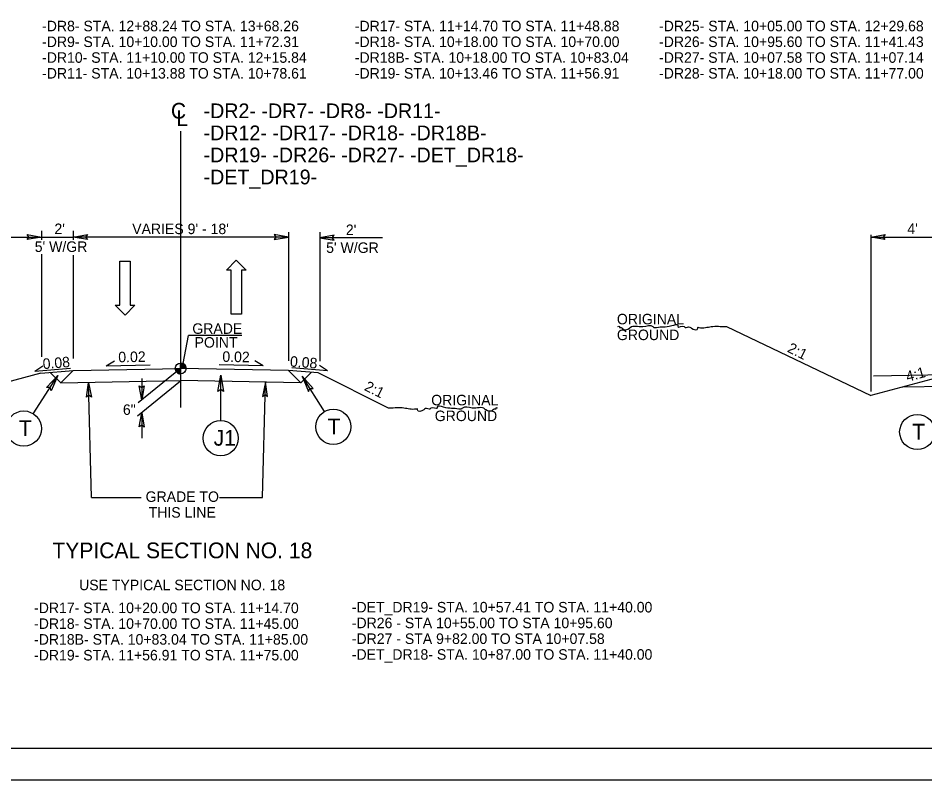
# Model space of a CAD drawing. Extents: x 18938 to 19565, y 6931 to 7973.
# Drawn here: x 19231 to 19317.4, y 6930.7 to 7003.2 of the extents above; entities that cross this region are included whole.
import ezdxf

# ---------------------------------------------------------------- set-up
doc = ezdxf.new("R2010")
doc.units = 0
for name, color, linetype in [('Old_Level_11', 7, 'Continuous'), ('Old_Level_2', 7, 'Continuous'), ('Old_Level_3', 7, 'Continuous'), ('Prop Dimension', 7, 'Continuous'), ('Prop Pavement Schedule Description CELL', 7, 'Continuous'), ('Prop Shade Medium', 7, 'Continuous'), ('Prop Terminator CELL', 7, 'Continuous'), ('Sheet Data Field CELL', 7, 'Continuous'), ('Sheet Plot Border Outside CELL', 7, 'Continuous'), ('Sheet Typical CELL', 7, 'Continuous'), ('Typical Curb CELL', 7, 'Continuous'), ('Typical Detail Wedge1 CELL', 7, 'Continuous'), ('Typical Detail Wedge2 CELL', 7, 'Continuous'), ('Typical Detail Wedge3 CELL', 7, 'Continuous'), ('Typical Guardrail CELL', 7, 'Continuous'), ('Typical Pavement Slope Information CELL', 7, 'Continuous'), ('Typical Shoulder Slope Information CELL', 7, 'Continuous'), ('Typical Terminator CELL', 7, 'Continuous'), ('Typical Text General CELL', 7, 'Continuous'), ('Typical Text Grade Point CELL', 7, 'Continuous'), ('Typical Text ID Circle CELL', 7, 'Continuous'), ('Typical Text Label CELL', 7, 'Continuous')]:
    doc.layers.add(name, color=color, linetype=linetype)

msp = doc.modelspace()

# ---------------------------------------------------------------- linework, layer by layer
at = {"layer": 'Old_Level_3'}
msp.add_line((19234.277, 6982.344), (19236.277, 6982.344), dxfattribs=at)
at = {"layer": 'Prop Dimension'}
msp.add_lwpolyline([(19155.167, 6930.669), (19382.434, 6930.669), (19382.434, 7077.102), (19155.167, 7077.102)], close=True, dxfattribs=at)
at = {"layer": 'Prop Pavement Schedule Description CELL'}
for p, q in [((19233.191, 6969.387), (19236.277, 6969.634)), ((19235.099, 6968.456), (19234.096, 6969.459)), ((19235.099, 6968.456), (19236.277, 6969.634)), ((19236.277, 6969.634), (19246.511, 6969.838)), ((19256.764, 6969.633), (19246.51, 6969.838)), ((19259.617, 6969.405), (19256.764, 6969.633)), ((19257.939, 6968.458), (19256.764, 6969.633)), ((19257.939, 6968.458), (19258.941, 6969.459)), ((19266.312, 6966.058), (19259.617, 6969.405)), ((19235.099, 6968.456), (19246.51, 6968.684)), ((19239.01, 6968.526), (19239.01, 6968.522)), ((19257.939, 6968.458), (19246.51, 6968.684)), ((19254.01, 6968.526), (19254.01, 6968.522)), ((19315.254, 6968.07), (19333.221, 6968.429))]:
    msp.add_line(p, q, dxfattribs=at)
at = {"layer": 'Prop Shade Medium'}
for p, q in [((19298.488, 6973.825), (19312.221, 6967.255)), ((19233.191, 6969.387), (19225.255, 6967.255)), ((19320.157, 6969.387), (19312.221, 6967.255))]:
    msp.add_line(p, q, dxfattribs=at)
at = {"layer": 'Sheet Data Field CELL'}
for points in [[(19231.905, 6982.576), (19233.255, 6982.344), (19231.898, 6982.104), (19232.07, 6982.344)], [(19237.627, 6982.111), (19236.277, 6982.344), (19237.634, 6982.584), (19237.462, 6982.344)], [(19255.414, 6982.111), (19256.764, 6982.344), (19255.406, 6982.584), (19255.579, 6982.344)], [(19261.115, 6982.515), (19259.765, 6982.282), (19261.123, 6982.042), (19260.95, 6982.282)], [(19313.571, 6982.111), (19312.221, 6982.344), (19313.579, 6982.584), (19313.406, 6982.344)], [(19254.792, 6967.169), (19254.596, 6968.525), (19254.319, 6967.174), (19254.564, 6967.34)], [(19237.552, 6967.104), (19237.75, 6968.46), (19238.025, 6967.109), (19237.781, 6967.275)], [(19243.034, 6968.184), (19242.801, 6966.834), (19242.561, 6968.191), (19242.801, 6968.019)], [(19242.569, 6964.26), (19242.802, 6965.61), (19243.042, 6964.253), (19242.802, 6964.425)]]:
    msp.add_lwpolyline(points, close=True, dxfattribs=at)
at = {"layer": 'Sheet Typical CELL'}
for p, q in [((19225.255, 6982.344), (19234.277, 6982.344)), ((19233.255, 6982.918), (19233.255, 6982.086)), ((19236.277, 6982.918), (19236.277, 6982.086)), ((19256.764, 6982.344), (19236.277, 6982.344)), ((19256.764, 6982.804), (19256.764, 6970.571)), ((19259.765, 6982.794), (19259.765, 6970.53)), ((19312.221, 6982.549), (19312.221, 6967.623)), ((19312.221, 6982.344), (19321.243, 6982.344)), ((19265.735, 6982.282), (19259.765, 6982.282)), ((19233.255, 6980.704), (19233.255, 6970.943)), ((19236.277, 6980.632), (19236.277, 6970.765)), ((19246.511, 6969.838), (19242.455, 6966.554)), ((19246.511, 6968.614), (19242.406, 6965.289)), ((19242.801, 6968.877), (19242.801, 6966.834)), ((19238.033, 6957.555), (19237.75, 6968.46)), ((19254.299, 6957.555), (19254.594, 6968.463)), ((19242.802, 6965.61), (19242.802, 6963.181)), ((19238.033, 6957.555), (19242.738, 6957.555)), ((19250.216, 6957.555), (19254.299, 6957.555))]:
    msp.add_line(p, q, dxfattribs=at)
at = {"layer": 'Typical Curb CELL'}
for points in [[(19288.124, 6973.825), (19288.295, 6973.825), (19288.295, 6973.739), (19288.467, 6973.739), (19288.552, 6973.653), (19289.238, 6973.653), (19289.323, 6973.739), (19290.522, 6973.825), (19291.464, 6973.825), (19291.55, 6973.739), (19291.807, 6973.739), (19293.263, 6973.91), (19293.863, 6973.91), (19293.863, 6973.825), (19294.462, 6973.825), (19294.548, 6973.739), (19294.634, 6973.739), (19295.062, 6973.739), (19295.148, 6973.653), (19295.747, 6973.653), (19295.747, 6973.739), (19295.833, 6973.739), (19297.032, 6973.825), (19298.402, 6973.825), (19298.488, 6973.825)], [(19276.676, 6966.058), (19276.504, 6966.058), (19276.504, 6965.972), (19276.333, 6965.972), (19276.248, 6965.886), (19275.562, 6965.886), (19275.477, 6965.972), (19274.277, 6966.058), (19273.335, 6966.058), (19273.25, 6965.972), (19272.993, 6965.972), (19271.537, 6966.143), (19270.937, 6966.143), (19270.937, 6966.058), (19270.337, 6966.058), (19270.252, 6965.972), (19270.166, 6965.972), (19269.738, 6965.972), (19269.652, 6965.886), (19269.053, 6965.886), (19269.053, 6965.972), (19268.967, 6965.972), (19267.768, 6966.058), (19266.397, 6966.058), (19266.312, 6966.058)]]:
    msp.add_spline(points, degree=3, dxfattribs=at)
at = {"layer": 'Typical Detail Wedge1 CELL'}
for p, q in [((19246.511, 6969.838), (19246.511, 6970.35)), ((19245.998, 6969.838), (19246.511, 6969.838)), ((19246.51, 6969.326), (19246.511, 6969.838)), ((19246.511, 6969.838), (19246.51, 6969.326)), ((19247.022, 6969.838), (19246.511, 6969.838))]:
    msp.add_line(p, q, dxfattribs=at)
for points in [[(19246.515, 6970.35), (19246.515, 6970.35), (19246.515, 6969.838)], [(19246.526, 6970.35), (19246.525, 6969.838)], [(19246.536, 6970.349), (19246.536, 6969.838)], [(19246.546, 6970.349), (19246.546, 6969.838)], [(19246.556, 6970.348), (19246.556, 6969.838)], [(19246.567, 6970.347), (19246.567, 6969.838)], [(19246.577, 6970.346), (19246.577, 6969.838)], [(19246.587, 6970.345), (19246.587, 6969.838)], [(19246.598, 6970.343), (19246.597, 6969.838)], [(19246.608, 6970.341), (19246.608, 6969.838)], [(19246.618, 6970.339), (19246.618, 6969.838)], [(19246.628, 6970.336), (19246.628, 6969.838)], [(19246.639, 6970.334), (19246.638, 6969.838)], [(19246.649, 6970.331), (19246.649, 6969.838)], [(19246.659, 6970.328), (19246.659, 6969.838)], [(19246.669, 6970.325), (19246.669, 6969.838)], [(19246.68, 6970.322), (19246.679, 6969.838)], [(19246.69, 6970.318), (19246.689, 6969.838)], [(19246.7, 6970.314), (19246.7, 6969.838)], [(19246.71, 6970.31), (19246.71, 6969.838)], [(19246.72, 6970.305), (19246.72, 6969.838)], [(19246.73, 6970.301), (19246.73, 6969.838)], [(19246.741, 6970.296), (19246.741, 6969.838)], [(19246.751, 6970.29), (19246.751, 6969.838)], [(19246.761, 6970.284), (19246.761, 6969.838)], [(19246.771, 6970.279), (19246.771, 6969.838)], [(19246.782, 6970.273), (19246.782, 6969.838)], [(19246.792, 6970.266), (19246.792, 6969.838)], [(19246.802, 6970.259), (19246.802, 6969.838)], [(19246.813, 6970.252), (19246.813, 6969.838)], [(19246.823, 6970.244), (19246.823, 6969.838)], [(19246.833, 6970.236), (19246.833, 6969.838)], [(19246.001, 6969.838), (19246.001, 6969.782)], [(19246.012, 6969.838), (19246.012, 6969.722)], [(19246.022, 6969.838), (19246.022, 6969.685)], [(19246.032, 6969.838), (19246.032, 6969.655)], [(19246.042, 6969.838), (19246.042, 6969.63)], [(19246.052, 6969.838), (19246.052, 6969.609)], [(19246.063, 6969.838), (19246.063, 6969.589)], [(19246.073, 6969.838), (19246.073, 6969.572)], [(19246.083, 6969.838), (19246.083, 6969.556)], [(19246.094, 6969.838), (19246.094, 6969.541)], [(19246.104, 6969.838), (19246.104, 6969.527)], [(19246.114, 6969.838), (19246.114, 6969.514)], [(19246.124, 6969.838), (19246.124, 6969.502)], [(19246.135, 6969.838), (19246.135, 6969.49)], [(19246.145, 6969.838), (19246.145, 6969.48)], [(19246.155, 6969.838), (19246.155, 6969.47)], [(19246.165, 6969.838), (19246.165, 6969.46)], [(19246.176, 6969.838), (19246.175, 6969.451)], [(19246.186, 6969.838), (19246.186, 6969.442)], [(19246.196, 6969.838), (19246.196, 6969.434)], [(19246.206, 6969.838), (19246.206, 6969.427)], [(19246.216, 6969.838), (19246.216, 6969.419)], [(19246.227, 6969.838), (19246.226, 6969.412)], [(19246.237, 6969.838), (19246.237, 6969.405)], [(19246.247, 6969.838), (19246.247, 6969.399)], [(19246.257, 6969.838), (19246.257, 6969.393)], [(19246.267, 6969.838), (19246.267, 6969.387)], [(19246.278, 6969.838), (19246.278, 6969.382)], [(19246.288, 6969.838), (19246.288, 6969.377)], [(19246.298, 6969.838), (19246.298, 6969.372)], [(19246.309, 6969.838), (19246.309, 6969.368)], [(19246.319, 6969.838), (19246.319, 6969.363)], [(19246.329, 6969.838), (19246.329, 6969.359)], [(19246.34, 6969.838), (19246.34, 6969.356)], [(19246.35, 6969.838), (19246.35, 6969.352)], [(19246.36, 6969.838), (19246.36, 6969.349)], [(19246.37, 6969.838), (19246.37, 6969.346)], [(19246.38, 6969.838), (19246.38, 6969.343)], [(19246.391, 6969.838), (19246.39, 6969.341)], [(19246.401, 6969.838), (19246.401, 6969.338)], [(19246.411, 6969.838), (19246.411, 6969.336)], [(19246.421, 6969.838), (19246.421, 6969.334)], [(19246.431, 6969.838), (19246.431, 6969.332)], [(19246.442, 6969.838), (19246.442, 6969.331)], [(19246.452, 6969.838), (19246.452, 6969.33)], [(19246.462, 6969.838), (19246.462, 6969.328)], [(19246.472, 6969.838), (19246.472, 6969.328)], [(19246.483, 6969.838), (19246.483, 6969.327)], [(19246.493, 6969.838), (19246.493, 6969.327)], [(19246.503, 6969.838), (19246.503, 6969.326), (19246.503, 6969.326)], [(19246.843, 6970.227), (19246.843, 6969.838)], [(19246.854, 6970.218), (19246.853, 6969.838)], [(19246.864, 6970.209), (19246.864, 6969.838)], [(19246.874, 6970.199), (19246.874, 6969.838)], [(19246.884, 6970.188), (19246.884, 6969.838)], [(19246.894, 6970.177), (19246.894, 6969.838)], [(19246.905, 6970.165), (19246.904, 6969.838)], [(19246.915, 6970.152), (19246.915, 6969.838)], [(19246.925, 6970.139), (19246.925, 6969.838)], [(19246.935, 6970.124), (19246.935, 6969.838)], [(19246.945, 6970.108), (19246.945, 6969.838)], [(19246.956, 6970.091), (19246.956, 6969.838)], [(19246.966, 6970.072), (19246.966, 6969.838)], [(19246.976, 6970.05), (19246.976, 6969.838)], [(19246.987, 6970.027), (19246.987, 6969.838)], [(19246.997, 6969.998), (19246.997, 6969.838)], [(19247.007, 6969.963), (19247.007, 6969.838)], [(19247.017, 6969.911), (19247.017, 6969.838)]]:
    msp.add_lwpolyline(points, dxfattribs=at)
msp.add_circle((19246.51, 6969.838), 0.512, dxfattribs=at)
for start, end in [(359.99048, 89.99048), (179.99048, 269.99048)]:
    msp.add_arc((19246.51, 6969.838), 0.512, start, end, dxfattribs=at)
at = {"layer": 'Typical Detail Wedge3 CELL'}
for p, q in [((19240.717, 6975.857), (19240.717, 6980.057)), ((19240.717, 6980.057), (19241.707, 6980.057)), ((19241.707, 6980.057), (19241.707, 6975.857)), ((19250.863, 6979.186), (19251.793, 6980.131)), ((19251.793, 6980.131), (19252.753, 6979.186)), ((19251.313, 6979.186), (19250.863, 6979.186)), ((19251.313, 6974.986), (19251.313, 6979.186)), ((19252.753, 6979.186), (19252.303, 6979.186)), ((19252.303, 6979.186), (19252.303, 6974.986)), ((19241.227, 6974.912), (19240.267, 6975.857)), ((19240.267, 6975.857), (19240.717, 6975.857)), ((19242.157, 6975.857), (19241.227, 6974.912)), ((19241.707, 6975.857), (19242.157, 6975.857)), ((19252.303, 6974.986), (19251.313, 6974.986))]:
    msp.add_line(p, q, dxfattribs=at)
at = {"layer": 'Typical Guardrail CELL'}
msp.add_line((19312.48, 6969.124), (19323.223, 6969.338), dxfattribs=at)
at = {"layer": 'Typical Pavement Slope Information CELL'}
msp.add_lwpolyline([(19380.142, 7074.095), (19177.642, 7074.095), (19177.642, 6933.679), (19380.142, 6933.679)], close=True, dxfattribs=at)
at = {"layer": 'Typical Terminator CELL'}
for p, q in [((19232.477, 6965.523), (19234.803, 6969.176)), ((19250.326, 6964.869), (19250.326, 6969.2)), ((19260.214, 6965.732), (19258.076, 6969.089))]:
    msp.add_line(p, q, dxfattribs=at)
for centre in [(19261.048, 6964.278), (19231.577, 6964.109), (19316.642, 6963.784), (19250.326, 6963.193)]:
    msp.add_circle(centre, 1.676, dxfattribs=at)
at = {"layer": 'Typical Text General CELL'}
for points in [[(19233.744, 6968.011), (19234.803, 6969.176), (19234.198, 6967.712), (19234.072, 6968.027)], [(19250.059, 6967.648), (19250.326, 6969.2), (19250.602, 6967.64), (19250.326, 6967.838)], [(19259.135, 6967.924), (19258.076, 6969.089), (19258.682, 6967.625), (19258.808, 6967.94)]]:
    msp.add_lwpolyline(points, close=True, dxfattribs=at)
at = {"layer": 'Typical Text Grade Point CELL'}
for p, q in [((19239.415, 6970.079), (19240.198, 6970.552)), ((19254.359, 6970.079), (19253.576, 6970.552)), ((19232.626, 6969.577), (19233.379, 6970.096)), ((19232.626, 6969.577), (19236.012, 6969.848)), ((19239.415, 6970.079), (19243.603, 6970.162)), ((19254.359, 6970.079), (19250.17, 6970.162)), ((19260.495, 6969.609), (19257.109, 6969.88)), ((19260.495, 6969.609), (19259.742, 6970.128))]:
    msp.add_line(p, q, dxfattribs=at)
at = {"layer": 'Typical Text ID Circle CELL'}
for p, q in [((19246.51, 6992.418), (19246.51, 6982.344)), ((19246.51, 6982.344), (19246.51, 6966.102)), ((19246.76, 6970.291), (19247.256, 6972.959)), ((19252.333, 6972.959), (19247.256, 6972.959))]:
    msp.add_line(p, q, dxfattribs=at)

# ---------------------------------------------------------------- texts
at = {"layer": 'Old_Level_11'}
for s, height, p in [('TYPICAL SECTION NO. 18', 1.5, (19234.299, 6951.764)), ('USE TYPICAL SECTION NO. 18', 1, (19236.843, 6948.722))]:
    msp.add_text(s, height=height, dxfattribs=at).set_placement(p)
at = {"layer": 'Old_Level_2'}
for s, p in [('ORIGINAL', (19288.047, 6974.031)), ('GROUND', (19288.047, 6972.531))]:
    msp.add_text(s, height=1, rotation=360, dxfattribs=at).set_placement(p)
for s, p in [('ORIGINAL', (19270.368, 6966.321)), ('GROUND', (19270.705, 6964.821))]:
    msp.add_text(s, height=1, dxfattribs=at).set_placement(p)
at = {"layer": 'Prop Terminator CELL'}
for s, p in [('T', (19260.503, 6963.558)), ('J1', (19249.654, 6962.481))]:
    msp.add_text(s, height=1.5, dxfattribs=at).set_placement(p)
for p in [(19231.108, 6963.389), (19316.173, 6963.064)]:
    msp.add_text('T', height=1.5, rotation=360, dxfattribs=at).set_placement(p)
at = {"layer": 'Sheet Plot Border Outside CELL'}
for s, p in [('GRADE', (19247.621, 6973.128)), ('POINT', (19247.839, 6971.817))]:
    msp.add_text(s, height=1, rotation=0.00004, dxfattribs=at).set_placement(p)
at = {"layer": 'Typical Detail Wedge2 CELL'}
for s, p in [('-DR8- STA. 12+88.24 TO STA. 13+68.26', (19233.318, 7001.93)), ('-DR17- STA. 11+14.70 TO STA. 11+48.88', (19263.091, 7001.93)), ('-DR25- STA. 10+05.00 TO STA. 12+29.68', (19292.06, 7001.93)), ('-DR9- STA. 10+10.00 TO STA. 11+72.31', (19233.318, 7000.43)), ('-DR18- STA. 10+18.00 TO STA. 10+70.00', (19263.091, 7000.43)), ('-DR26- STA. 10+95.60 TO STA. 11+41.43', (19292.06, 7000.43)), ('-DR10- STA. 11+10.00 TO STA. 12+15.84', (19233.318, 6998.93)), ('-DR18B- STA. 10+18.00 TO STA. 10+83.04', (19263.091, 6998.93)), ('-DR27- STA. 10+07.58 TO STA. 11+07.14', (19292.06, 6998.93)), ('-DR11- STA. 10+13.88 TO STA. 10+78.61', (19233.318, 6997.43)), ('-DR19- STA. 10+13.46 TO STA. 11+56.91', (19263.091, 6997.43)), ('-DR28- STA. 10+18.00 TO STA. 11+77.00', (19292.06, 6997.43)), ("2'", (19234.494, 6982.626)), ("VARIES 9' - 18'", (19241.897, 6982.62)), ("2'", (19262.24, 6982.532)), ("4'", (19315.698, 6982.633)), ("5' W/GR", (19232.618, 6980.926)), ("5' W/GR", (19260.364, 6980.832)), ('6"', (19241.015, 6965.413)), ('GRADE TO', (19243.175, 6957.129)), ('THIS LINE', (19243.466, 6955.629)), ('-DR17- STA. 10+20.00 TO STA. 11+14.70', (19232.555, 6946.54)), ('-DET_DR19- STA. 10+57.41 TO STA. 11+40.00', (19262.805, 6946.607)), ('-DR26 - STA 10+55.00 TO STA 10+95.60', (19262.805, 6945.107)), ('-DR18- STA. 10+70.00 TO STA. 11+45.00', (19232.555, 6945.04)), ('-DR18B- STA. 10+83.04 TO STA. 11+85.00', (19232.555, 6943.54)), ('-DR27 - STA 9+82.00 TO STA 10+07.58', (19262.805, 6943.607)), ('-DR19- STA. 11+56.91 TO STA. 11+75.00', (19232.555, 6942.04)), ('-DET_DR18- STA. 10+87.00 TO STA. 11+40.00', (19262.805, 6942.107))]:
    msp.add_text(s, height=1, dxfattribs=at).set_placement(p)
at = {"layer": 'Typical Shoulder Slope Information CELL'}
for s, rotation, p in [('2:1', 333.43491, (19304.197, 6971.447)), ('4:1', 15.1346, (19315.712, 6968.554)), ('2:1', 333.43491, (19263.923, 6967.797))]:
    msp.add_text(s, height=1, rotation=rotation, dxfattribs=at).set_placement(p)
at = {"layer": 'Typical Text Grade Point CELL'}
for s, rotation, p in [('0.02', 1.14574, (19240.582, 6970.413)), ('0.02', 358.85426, (19250.474, 6970.468)), ('0.08', 4.5738, (19233.414, 6969.765)), ('0.08', 355.4262, (19256.891, 6970.023))]:
    msp.add_text(s, height=1, rotation=rotation, dxfattribs=at).set_placement(p)
at = {"layer": 'Typical Text Label CELL'}
for s, height, p in [('C', 1.5, (19245.581, 6993.609)), ('-DR2- -DR7- -DR8- -DR11- ', 1.4, (19248.69, 6993.659)), ('L', 1.5, (19246.098, 6992.902)), ('-DR12- -DR17- -DR18- -DR18B- ', 1.4, (19248.69, 6991.559)), ('-DR19- -DR26- -DR27- -DET_DR18-', 1.4, (19248.69, 6989.459)), ('-DET_DR19-', 1.4, (19248.69, 6987.359))]:
    msp.add_text(s, height=height, dxfattribs=at).set_placement(p)

doc.saveas('drawing.dxf')
